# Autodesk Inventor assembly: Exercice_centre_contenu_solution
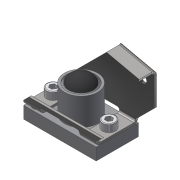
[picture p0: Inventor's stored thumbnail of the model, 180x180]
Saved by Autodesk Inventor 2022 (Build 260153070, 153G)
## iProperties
Created: 2018-06
Part Number: Exercice_centre_contenu_solution
Material: Générique
Document SubType Name: Assembly
Designer: Fabian Perrée
Mass: 105.136 g
Surface Area: 173.547 cm^2
Volume: 19.7524 cm^3
Density: 5.32267 g/cm^3
Author: Fabian Perrée
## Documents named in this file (5)
- C:\Users\Fabian\Google Drive\01_Giup\01_Clients\07_ENI\Manuscrit\Fichiers_exercice\Chapitre_06\Exercice_Centre_contenu\Exercice_centre_contenu_solution.iam
- C:\Users\Fabian\Google Drive\01_Giup\01_Clients\07_ENI\Manuscrit\Fichiers_exercice\Chapitre_06\Exercice_Centre_contenu\Composants\Etrier_tole.ipt
- C:\Users\Fabian\Google Drive\01_Giup\01_Clients\07_ENI\Manuscrit\Fichiers_exercice\CC\ISO 4762 - M5 x 8ISO.ipt
- C:\Users\Fabian\Google Drive\01_Giup\01_Clients\07_ENI\Manuscrit\Fichiers_exercice\Chapitre_06\Exercice_Centre_contenu\Composants\Chapeau_capteur.ipt
- C:\Users\Fabian\Google Drive\01_Giup\01_Clients\07_ENI\Manuscrit\Fichiers_exercice\Chapitre_06\Exercice_Centre_contenu\Composants\Bille_18.ipt
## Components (5 placed, 4 different names)
1. Etrier_tole:1 — Logement:3, Logement:4
2. Chapeau_capteur:1 — Logement:3, Logement:4
3. Bille_18:1
4. ISO 4762 M5 x 8:1
5. ISO 4762 M5 x 8:2
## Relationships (2: Insert 2)
- Logement:3 [Insert]: Etrier_tole:1 ↔ Chapeau_capteur:1
- Logement:4 [Insert]: Etrier_tole:1 ↔ Chapeau_capteur:1
